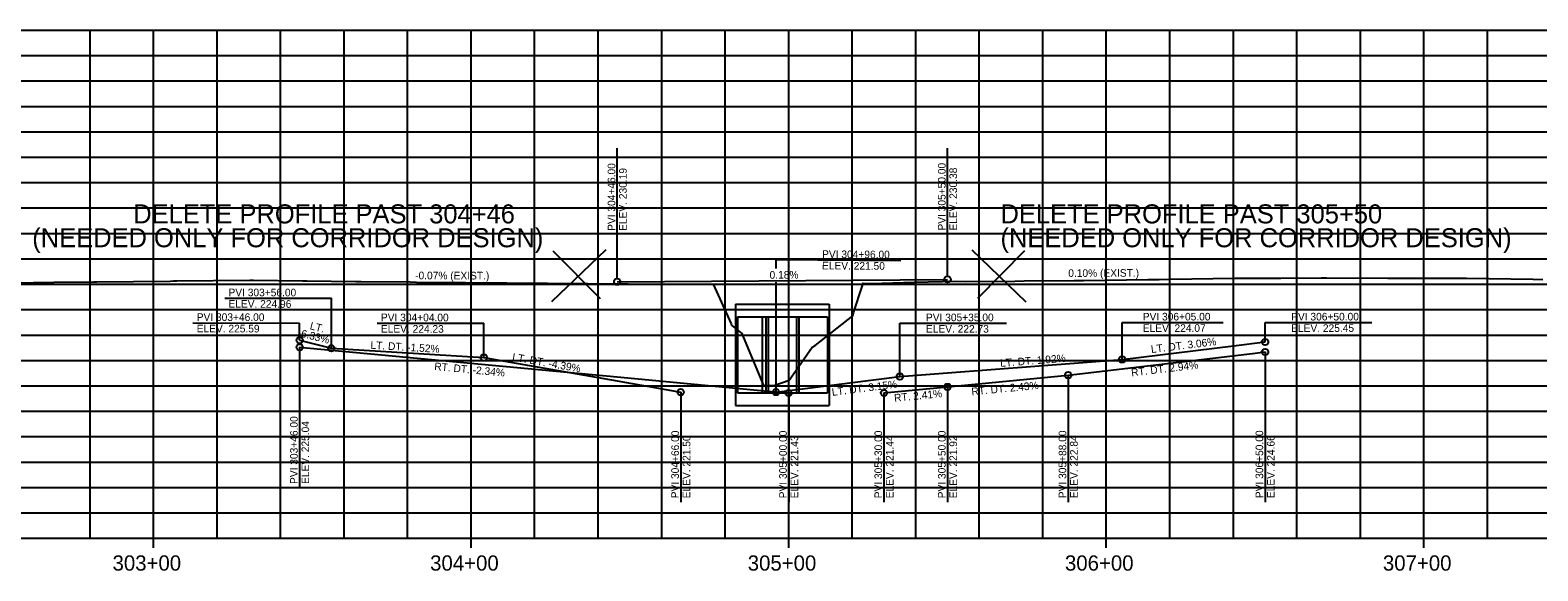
# Model space of a CAD drawing. Extents: x 1811793 to 1813336, y 532176 to 533566.
# Drawn here: x 1812275.4 to 1812750.1, y 532897.6 to 533067.9 of the extents above; entities that cross this region are included whole.
import ezdxf

# ---------------------------------------------------------------- set-up
doc = ezdxf.new("R2010")
doc.units = 0
for name, color, linetype in [('R_Axis', 7, 'Continuous'), ('R_Axis Annot', 7, 'Continuous'), ('R_Concrete', 7, 'Continuous'), ('R_Exist Surface', 7, 'Continuous'), ('R_Grid', 7, 'Continuous'), ('R_No Plot', 7, 'Continuous'), ('R_Vert Alg', 7, 'Continuous'), ('R_Vert Alg Annot', 7, 'Continuous')]:
    doc.layers.add(name, color=color, linetype=linetype)

msp = doc.modelspace()

# ---------------------------------------------------------------- linework, layer by layer
at = {"layer": 'R_Axis'}
msp.add_line((1812014.24, 532907.89), (1813014.24, 532907.89), dxfattribs=at)
at = {"layer": 'R_Concrete'}
for p, q in [((1812497.49, 532981.61), (1812497.49, 532949.69)), ((1812497.49, 532981.61), (1812526.99, 532981.61)), ((1812526.99, 532981.61), (1812526.99, 532949.69)), ((1812498.07, 532977.65), (1812526.4, 532977.65)), ((1812498.07, 532977.65), (1812498.07, 532953.65)), ((1812507.07, 532977.65), (1812507.07, 532953.65)), ((1812507.74, 532977.65), (1812507.74, 532953.65)), ((1812516.74, 532977.65), (1812516.74, 532953.65)), ((1812517.4, 532977.65), (1812517.4, 532953.65)), ((1812526.4, 532977.65), (1812526.4, 532953.65)), ((1812498.07, 532953.65), (1812526.4, 532953.65)), ((1812497.49, 532949.69), (1812526.99, 532949.69))]:
    msp.add_line(p, q, dxfattribs=at)
at = {"layer": 'R_Exist Surface'}
for points in [[(1812270.02, 532988.28), (1812282.86, 532988.48), (1812295.48, 532988.67), (1812296.43, 532988.68), (1812319.51, 532988.89), (1812320.55, 532988.9), (1812321.6, 532988.9), (1812344.55, 532989.11), (1812345.68, 532989.12), (1812361.12, 532988.93), (1812362.56, 532988.95), (1812377.89, 532988.76), (1812379.44, 532988.79), (1812379.61, 532988.78), (1812395.02, 532988.59), (1812397.05, 532988.57), (1812412.41, 532988.39), (1812412.79, 532988.37), (1812414.14, 532988.37), (1812425.52, 532988.27), (1812436.77, 532988.18), (1812438.25, 532988.17), (1812449.46, 532988.08), (1812450.99, 532988.07), (1812462.15, 532987.98), (1812463.73, 532987.98), (1812475.43, 532987.91), (1812477.1, 532987.93), (1812488.78, 532987.87), (1812490.48, 532987.88), (1812496.11, 532975.44), (1812496.25, 532974.98), (1812496.3, 532974.9), (1812499.47, 532972.32), (1812499.87, 532971.27), (1812506.35, 532956.02), (1812506.43, 532956.04), (1812509.62, 532956.02), (1812509.87, 532956.1), (1812514.33, 532957.7), (1812514.89, 532958.37), (1812521.66, 532968.11), (1812522.52, 532968.58), (1812534.38, 532977.88), (1812534.68, 532978.86), (1812537.43, 532987.47)], [(1812537.43, 532987.47), (1812537.66, 532988.2), (1812540.31, 532988.16), (1812553.71, 532988.5), (1812567.1, 532988.83), (1812569.75, 532988.79), (1812585.41, 532988.88), (1812588.41, 532988.93), (1812604.07, 532989.02), (1812607.07, 532989.07), (1812627.3, 532989.35), (1812630.89, 532989.42), (1812634.37, 532989.48), (1812654.72, 532989.76), (1812656.84, 532989.76), (1812669.17, 532989.83), (1812681.94, 532989.91), (1812683.6, 532989.91), (1812702.91, 532989.82), (1812705.62, 532989.83), (1812724.71, 532989.75), (1812727.63, 532989.75), (1812748.61, 532989.44), (1812751.74, 532989.39)]]:
    msp.add_lwpolyline(points, dxfattribs=at)
at = {"layer": 'R_Grid'}
for p, q in [((1812014.24, 533067.89), (1813014.24, 533067.89)), ((1812014.24, 533067.89), (1813014.24, 533067.89)), ((1812294.24, 532907.89), (1812294.24, 533067.89)), ((1812314.24, 532907.89), (1812314.24, 533067.89)), ((1812334.24, 532907.89), (1812334.24, 533067.89)), ((1812354.24, 532907.89), (1812354.24, 533067.89)), ((1812374.24, 532907.89), (1812374.24, 533067.89)), ((1812394.24, 532907.89), (1812394.24, 533067.89)), ((1812414.24, 532907.89), (1812414.24, 533067.89)), ((1812434.24, 532907.89), (1812434.24, 533067.89)), ((1812454.24, 532907.89), (1812454.24, 533067.89)), ((1812474.24, 532907.89), (1812474.24, 533067.89)), ((1812494.24, 532907.89), (1812494.24, 533067.89)), ((1812514.24, 532907.89), (1812514.24, 533067.89)), ((1812534.24, 532907.89), (1812534.24, 533067.89)), ((1812554.24, 532907.89), (1812554.24, 533067.89)), ((1812574.24, 532907.89), (1812574.24, 533067.89)), ((1812594.24, 532907.89), (1812594.24, 533067.89)), ((1812614.24, 532907.89), (1812614.24, 533067.89)), ((1812634.24, 532907.89), (1812634.24, 533067.89)), ((1812654.24, 532907.89), (1812654.24, 533067.89)), ((1812674.24, 532907.89), (1812674.24, 533067.89)), ((1812694.24, 532907.89), (1812694.24, 533067.89)), ((1812714.24, 532907.89), (1812714.24, 533067.89)), ((1812734.24, 532907.89), (1812734.24, 533067.89)), ((1812014.24, 533059.89), (1813014.24, 533059.89)), ((1812014.24, 533051.89), (1813014.24, 533051.89)), ((1812014.24, 533043.89), (1813014.24, 533043.89)), ((1812014.24, 533035.89), (1813014.24, 533035.89)), ((1812014.24, 533027.89), (1813014.24, 533027.89)), ((1812014.24, 533019.89), (1813014.24, 533019.89)), ((1812014.24, 533011.89), (1813014.24, 533011.89)), ((1812014.24, 533003.89), (1813014.24, 533003.89)), ((1812014.24, 532995.89), (1813014.24, 532995.89)), ((1812014.24, 532987.89), (1813014.24, 532987.89)), ((1812014.24, 532979.89), (1813014.24, 532979.89)), ((1812014.24, 532971.89), (1813014.24, 532971.89)), ((1812014.24, 532963.89), (1813014.24, 532963.89)), ((1812014.24, 532955.89), (1813014.24, 532955.89)), ((1812014.24, 532947.89), (1813014.24, 532947.89)), ((1812014.24, 532939.89), (1813014.24, 532939.89)), ((1812014.24, 532931.89), (1813014.24, 532931.89)), ((1812014.24, 532923.89), (1813014.24, 532923.89)), ((1812014.24, 532915.89), (1813014.24, 532915.89)), ((1812314.24, 532904.89), (1812314.24, 532907.89)), ((1812414.24, 532904.89), (1812414.24, 532907.89)), ((1812514.24, 532904.89), (1812514.24, 532907.89)), ((1812614.24, 532904.89), (1812614.24, 532907.89)), ((1812714.24, 532904.89), (1812714.24, 532907.89))]:
    msp.add_line(p, q, dxfattribs=at)
at = {"layer": 'R_No Plot'}
for p, q in [((1812456.63, 532998.67), (1812439.53, 532982.34)), ((1812439.96, 532998.41), (1812454.83, 532983.36)), ((1812571.85, 532998.67), (1812588.94, 532982.34)), ((1812588.51, 532998.41), (1812573.64, 532983.36)), ((1812505.91, 532977.65), (1812505.91, 532953.65))]:
    msp.add_line(p, q, dxfattribs=at)
at = {"layer": 'R_Vert Alg'}
msp.add_line((1812460.24, 532988.66), (1812564.24, 532989.42), dxfattribs=at)
at = {"layer": 'R_Vert Alg Annot'}
for p, q in [((1812460.24, 532989.66), (1812460.24, 533030.71)), ((1812564.24, 532990.42), (1812564.24, 533030.71)), ((1812510.24, 532995.66), (1812549.54, 532995.38)), ((1812510.24, 532992.81), (1812510.24, 532995.66)), ((1812510.24, 532953.9), (1812510.24, 532988.52)), ((1812336.64, 532983.52), (1812370.24, 532983.44)), ((1812370.24, 532967.72), (1812370.24, 532983.44)), ((1812326.64, 532975.74), (1812360.24, 532975.66)), ((1812360.24, 532970.25), (1812360.24, 532975.66)), ((1812384.64, 532975.64), (1812418.24, 532975.57)), ((1812418.24, 532964.8), (1812418.24, 532975.57)), ((1812549.24, 532958.81), (1812549.24, 532975.63)), ((1812549.24, 532975.63), (1812582.84, 532975.63)), ((1812619.24, 532964.19), (1812619.24, 532975.87)), ((1812619.24, 532975.87), (1812651.05, 532975.87)), ((1812664.24, 532969.69), (1812664.24, 532975.87)), ((1812664.24, 532975.87), (1812697.84, 532975.87)), ((1812360.24, 532970.25), (1812370.24, 532967.72)), ((1812654.24, 532968.47), (1812664.24, 532969.69)), ((1812360.24, 532968.04), (1812360.24, 532924.03)), ((1812360.24, 532968.04), (1812370.24, 532967.1)), ((1812370.24, 532967.72), (1812418.24, 532964.8)), ((1812370.24, 532967.1), (1812460.24, 532958.67)), ((1812418.24, 532964.8), (1812460.24, 532957.42)), ((1812602.24, 532959.25), (1812660.24, 532966.07)), ((1812619.24, 532964.19), (1812654.24, 532968.47)), ((1812660.24, 532966.07), (1812664.24, 532966.55)), ((1812664.24, 532966.55), (1812664.24, 532919.27)), ((1812549.24, 532958.81), (1812564.24, 532959.96)), ((1812564.24, 532959.96), (1812619.24, 532964.19)), ((1812460.24, 532958.67), (1812514.24, 532953.61)), ((1812460.24, 532957.42), (1812480.24, 532953.91)), ((1812510.24, 532953.9), (1812549.24, 532958.81)), ((1812544.24, 532953.63), (1812564.24, 532955.56)), ((1812564.24, 532955.56), (1812602.24, 532959.25)), ((1812564.24, 532955.56), (1812564.24, 532919.27)), ((1812602.24, 532959.25), (1812602.24, 532919.27)), ((1812480.24, 532953.91), (1812480.24, 532919.27)), ((1812514.24, 532953.61), (1812514.24, 532919.27)), ((1812544.24, 532953.63), (1812544.24, 532919.27))]:
    msp.add_line(p, q, dxfattribs=at)
for centre in [(1812460.24, 532988.66), (1812564.24, 532989.42), (1812360.24, 532970.25), (1812360.24, 532968.04), (1812664.24, 532969.69), (1812370.24, 532967.72), (1812418.24, 532964.8), (1812619.24, 532964.19), (1812664.24, 532966.55), (1812549.24, 532958.81), (1812602.24, 532959.25), (1812480.24, 532953.91), (1812510.24, 532953.9), (1812564.24, 532955.56), (1812514.24, 532953.61), (1812544.24, 532953.63)]:
    msp.add_circle(centre, 1, dxfattribs=at)

# ---------------------------------------------------------------- texts
at = {"layer": 'R_Axis Annot'}
for s, p in [('303+00', (1812301.33, 532897.69)), ('304+00', (1812401.33, 532897.69)), ('305+00', (1812501.33, 532897.69)), ('306+00', (1812601.22, 532897.69)), ('307+00', (1812701.33, 532897.69))]:
    msp.add_text(s, height=4.8, dxfattribs=at).set_placement(p)
at = {"layer": 'R_No Plot'}
for s, p in [('DELETE PROFILE PAST 304+46', (1812307.85, 533007.03)), ('DELETE PROFILE PAST 305+50', (1812580.92, 533007.03)), ('(NEEDED ONLY FOR CORRIDOR DESIGN)', (1812276.05, 532999.52)), ('(NEEDED ONLY FOR CORRIDOR DESIGN)', (1812580.92, 532999.52))]:
    msp.add_text(s, height=6, dxfattribs=at).set_placement(p)
at = {"layer": 'R_Vert Alg Annot'}
for s, rotation, p in [('PVI 305+50.00', 90, (1812563.64, 533004.78)), ('PVI 304+46.00', 90, (1812459.64, 533004.68)), ('ELEV. 230.19', 90, (1812463.24, 533004.68)), ('ELEV. 230.38', 90, (1812567.24, 533004.78)), ('PVI 304+96.00', 359.6039, (1812524.74, 532996.16)), ('ELEV. 221.50', 359.6039, (1812524.71, 532992.56)), ('0.10% (EXIST.)', 0.2182, (1812602.27, 532990.17)), ('-0.07% (EXIST.)', 359.844, (1812396.61, 532989.44)), ('0.18%', 0.419, (1812508.22, 532989.61)), ('PVI 303+56.00', 359.868, (1812337.84, 532984.11)), ('PVI 303+46.00', 359.868, (1812327.84, 532976.34)), ('ELEV. 224.96', 359.868, (1812337.83, 532980.51)), ('PVI 304+04.00', 359.868, (1812385.84, 532976.24)), ('ELEV. 225.59', 359.868, (1812327.83, 532972.74)), ('LT.', 345.7993, (1812363.29, 532973.73)), ('ELEV. 224.23', 359.868, (1812385.83, 532972.64)), ('-6.33%', 345.7993, (1812359.45, 532971.6)), ('LT. DT. -1.52%', 356.5217, (1812382.49, 532967.58)), ('LT. DT. 3.06%', 6.9744, (1812628.44, 532966.2)), ('LT. DT. -4.39%', 350.0361, (1812427.05, 532963.86)), ('LT. DT. 1.92%', 4.3924, (1812580.9, 532961.85)), ('RT. DT. -2.34%', 354.6474, (1812402.57, 532960.87)), ('RT. DT. 2.94%', 6.7077, (1812622.21, 532958.85)), ('LT. DT. 3.15%', 7.1789, (1812527.96, 532952.71)), ('RT. DT. 2.43%', 5.5498, (1812571.88, 532952.86)), ('RT. 2.41%', 5.5043, (1812547.54, 532950.87)), ('PVI 303+46.00', 90, (1812359.64, 532924.98)), ('ELEV. 225.04', 90, (1812363.24, 532924.98)), ('PVI 304+66.00', 89.868, (1812479.64, 532920.47)), ('PVI 305+00.00', 90, (1812513.64, 532920.46)), ('PVI 305+30.00', 90, (1812543.64, 532920.47)), ('PVI 305+50.00', 90, (1812563.64, 532920.47)), ('PVI 305+88.00', 90, (1812601.64, 532920.5)), ('PVI 306+50.00', 90, (1812663.64, 532920.52)), ('ELEV. 221.50', 89.868, (1812483.24, 532920.46)), ('ELEV. 221.43', 90, (1812517.24, 532920.46)), ('ELEV. 221.44', 90, (1812547.24, 532920.47)), ('ELEV. 221.92', 90, (1812567.24, 532920.47)), ('ELEV. 222.84', 90, (1812605.24, 532920.5)), ('ELEV. 224.66', 90, (1812667.24, 532920.52))]:
    msp.add_text(s, height=2.4, rotation=rotation, dxfattribs=at).set_placement(p)
for s, p in [('PVI 305+35.00', (1812557.45, 532976.23)), ('PVI 306+05.00', (1812625.72, 532976.47)), ('PVI 306+50.00', (1812672.45, 532976.47)), ('ELEV. 222.73', (1812557.45, 532972.63)), ('ELEV. 224.07', (1812625.72, 532972.87)), ('ELEV. 225.45', (1812672.45, 532972.87))]:
    msp.add_text(s, height=2.4, dxfattribs=at).set_placement(p)

doc.saveas('drawing.dxf')
